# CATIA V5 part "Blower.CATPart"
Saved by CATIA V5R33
Part number: Blower
Bounding box of the stored display mesh (mm): x -55 to 55, y -55 to 55, z -25 to 72.5
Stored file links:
  D:\PROJECTS\Project 2023\CATIA V5 6R 2023\Resources\Tutorial Files\c12_catia_v5_6r2023_tut\c12Tut1\Blower.CATPart
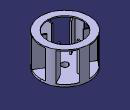
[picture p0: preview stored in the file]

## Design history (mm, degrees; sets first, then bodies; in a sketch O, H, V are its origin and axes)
Body1 (main body)
  Sketch1 on xy-plane, origin (0, 0, 0), H (1, 0, 0), V (0, 1, 0)
    circle A1 centre (0, 0) radius 55
    point P1 (0, 0)
    radius A1 = 55
    coincidence: P1 H, P1 O
  Pad1: profile Sketch1, direction (0, 0, 1), length 5
  Sketch2 on face of Pad1, origin (0, 0, 5), H (1, 0, 0), V (0, 1, 0)
    line L1 (0, 55) -> (0, 30)
    point P1 (0, 55)
    projected arc E1 centre (0, 0) radius 55 from (18.8111, 51.6831) to (0, 55) ccw from edge of Pad1
    line L2 (2.5, 53.4416) -> (2.5, 30)
    arc A1 centre (0, 0) radius 53.5 from (18.2981, 50.2736) to (2.5, 53.4416) ccw
    line L3 (0, 30) -> (2.5, 30)
    line L4 (18.2981, 50.2736) -> (18.8111, 51.6831)
    length L1 = 25
    distance L1 L2 = 2.5
    distance E1 A1 = 1.5
    angle L4 L1 = 20
    coincidence: P1 V, O L4
    vertical: L1 V
    concentricity: E1 A1
    horizontal: L3 H
  Pad2: profile Sketch2, direction (0, 0, 1), length 65
  CircPattern1: of Pad2, instances 6, angular step 60, axis from face of Pad1 from Sketch1.A1
  Sketch3 on face of Pad1, origin (0, 0, 0), H (1, 0, 0), V (0, -1, 0)
    circle A1 centre (0, 0) radius 15
    radius A1 = 15
  Pad3: profile Sketch3, direction (0, 0, -1), length 25
  Sketch4 on face of Pad2, origin (0, 0, 70), H (1, 0, 0), V (0, 1, 0)
    circle A1 centre (0, 0) radius 55
    radius A1 = 55
  Pad4: profile Sketch4, direction (0, 0, 1), length 2.5
  Sketch5 on face of Pad4, origin (0, 0, 72.5), H (1, 0, 0), V (0, 1, 0)
    circle A1 centre (0, 0) radius 40
    circle A2 centre (0, 0) radius 7.5
    radius A2 = 7.5
    radius A1 = 40
  MultiPocket1: profile Sketch5, domains (length 381; length 2.5)
  Sketch6 on yz-plane, origin (0, 0, 0), H (0, 1, 0), V (0, 0, 1)
    line L1 (0, 3.7002) -> (0, 148.5199)
    point P1 (0, 3.7002)
    coincidence: P1 V
    vertical: L1 V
